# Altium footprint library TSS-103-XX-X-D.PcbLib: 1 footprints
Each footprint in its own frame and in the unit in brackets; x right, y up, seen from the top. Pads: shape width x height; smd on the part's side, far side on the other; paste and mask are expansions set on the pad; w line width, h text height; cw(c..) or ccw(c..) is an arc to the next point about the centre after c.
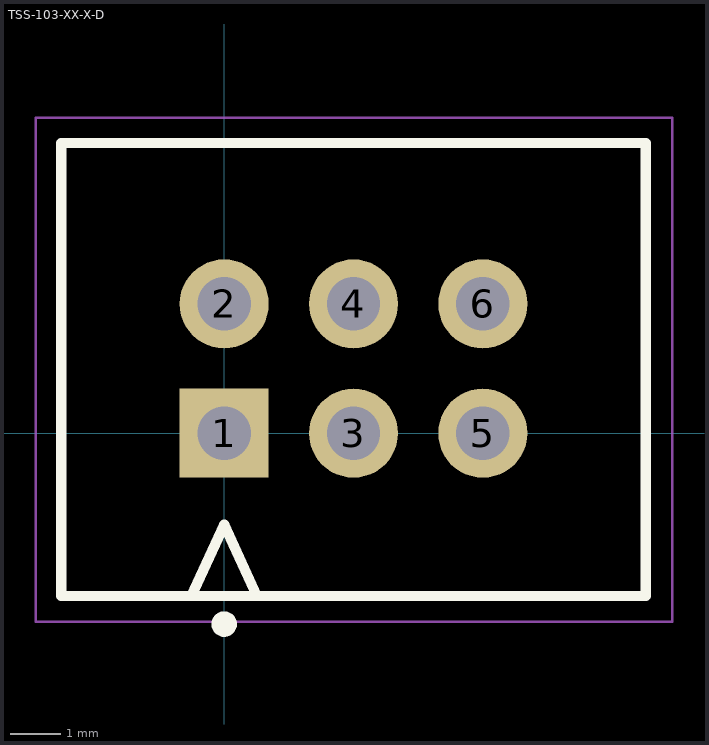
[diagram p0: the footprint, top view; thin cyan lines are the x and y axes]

## TSS-103-XX-X-D [mm] "2.54mm pitch, 6 pin, header; shrouded"
height 8.89
pads (6):
  rect 1.75x1.75 / inner round 1.75 / far side rect 1.75x1.75 hole 1.05 mask+0: 1(0,0)
  round 1.75 hole 1.05 mask+0: 2(0,2.54) 3(2.54,0) 4(2.54,2.54) 5(5.08,0) 6(5.08,2.54)
Top Overlay:
  circle w0.25: c0,-3.75 r0.125
  lines w0.2: -3.2,-3.2 8.28,-3.2 8.28,5.7 -3.2,5.7 -3.2,-3.2 ; -0.646,-3.2 0,-1.8 0.646,-3.2 -0.646,-3.2
Mechanical 12:
  lines w0.001: -3.2,-3.2 8.28,-3.2 8.28,5.7 -3.2,5.7 -3.2,-3.2
Mechanical 13:
  lines w0.1: -3.2,-3.2 8.28,-3.2 8.28,5.7 -3.2,5.7 -3.2,-3.2 ; -0.646,-3.2 0,-1.8 0.646,-3.2 -0.646,-3.2
  text ".Designator" at 0,0 h1.52
Mechanical 15:
  lines w0.05: -3.7,-3.7 8.8,-3.7 8.8,6.2 -3.7,6.2 -3.7,-3.7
